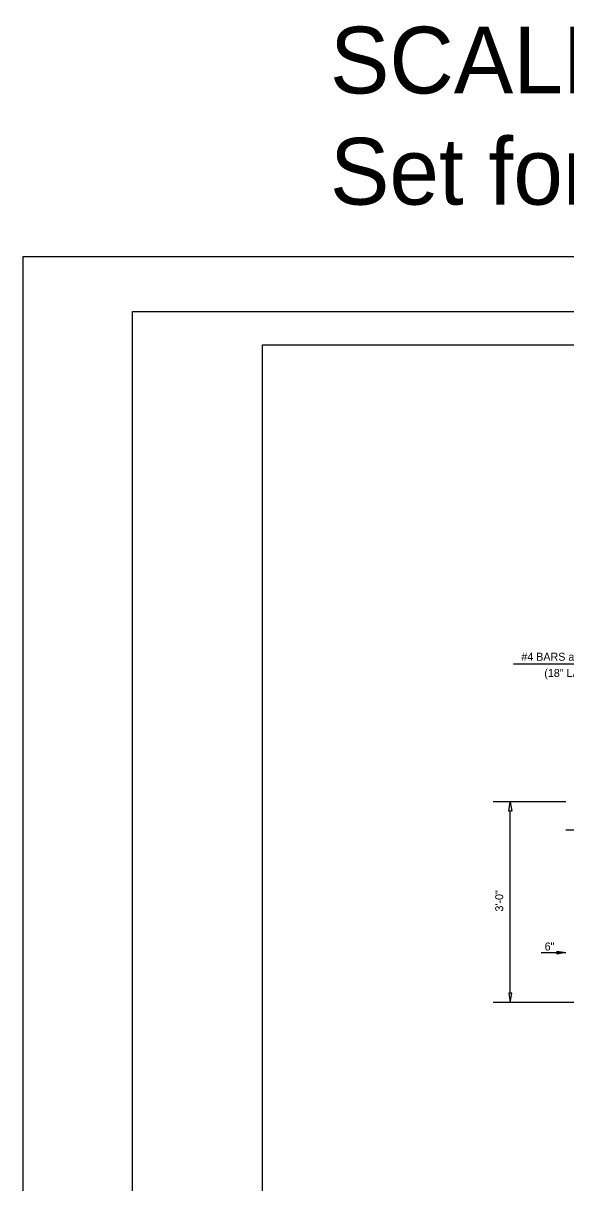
# Model space of a CAD drawing. Extents: x 570 to 2153298, y 726 to 139926.
# Drawn here: x 2153141.23 to 2153149.36, y 139607.73 to 139625.12 of the extents above; entities that cross this region are included whole.
import ezdxf

# ---------------------------------------------------------------- set-up
doc = ezdxf.new("R2010")
doc.units = 0
for name, color, linetype in [('4', 7, 'Continuous'), ('6', 7, 'Continuous'), ('Default', 7, 'Continuous'), ('PR_Dimensions', 7, 'Continuous'), ('PR_SlopeWall', 7, 'Continuous'), ('S', 7, 'Continuous'), ('SHT_Plot_Shape_Full', 7, 'Continuous'), ('SHT_Plot_Shape_Half', 7, 'Continuous'), ('SHT_Sheet_Border', 7, 'Continuous'), ('T', 7, 'Continuous')]:
    doc.layers.add(name, color=color, linetype=linetype)

# ---------------------------------------------------------------- blocks, each defined once
blk = doc.blocks.new('ARROWHD_15')
at = {"layer": 'Default'}
blk.add_lwpolyline([(0.0261, -0.0045), (0.0261, 0.0043), (-0.0004, -0.0001)], close=True, dxfattribs=at)

msp = doc.modelspace()

# ---------------------------------------------------------------- linework, layer by layer
at = {"layer": '4'}
msp.add_line((2153149.362, 139613.026), (2153149.862, 139613.026), dxfattribs=at)
at = {"layer": '6'}
for p, q in [((2153148.58, 139615.512), (2153151.721, 139615.512)), ((2153149.363, 139611.183), (2153148.994, 139611.183))]:
    msp.add_line(p, q, dxfattribs=at)
at = {"layer": 'Defpoints'}
for p, q in [((2153149.362, 139613.443), (2153148.275, 139613.443)), ((2153149.362, 139610.438), (2153148.275, 139610.438))]:
    msp.add_line(p, q, dxfattribs=at)
at = {"layer": 'PR_Dimensions'}
for p, q in [((2153149.323, 139613.443), (2153148.409, 139613.443)), ((2153148.529, 139610.578), (2153148.529, 139613.303)), ((2153149.242, 139610.438), (2153148.409, 139610.438))]:
    msp.add_line(p, q, dxfattribs=at)
for points in [[(2153148.552, 139613.303), (2153148.506, 139613.303), (2153148.529, 139613.443)], [(2153148.552, 139610.578), (2153148.506, 139610.578), (2153148.529, 139610.438)]]:
    msp.add_lwpolyline(points, close=True, dxfattribs=at)
at = {"layer": 'PR_SlopeWall'}
msp.add_line((2153150.362, 139610.438), (2153149.362, 139610.438), dxfattribs=at)
at = {"layer": 'SHT_Plot_Shape_Full'}
msp.add_lwpolyline([(2153141.225, 139621.622), (2153177.225, 139621.622), (2153177.225, 139597.622), (2153141.225, 139597.622)], close=True, dxfattribs=at)
at = {"layer": 'SHT_Plot_Shape_Half'}
msp.add_lwpolyline([(2153142.863, 139620.797), (2153176.863, 139620.797), (2153176.863, 139598.797), (2153142.863, 139598.797)], close=True, dxfattribs=at)
at = {"layer": 'SHT_Sheet_Border'}
msp.add_lwpolyline([(2153176.313, 139599.297), (2153144.813, 139599.297), (2153144.813, 139620.297), (2153176.313, 139620.297)], close=True, dxfattribs=at)

# ---------------------------------------------------------------- block references
at = {"layer": '6', "xscale": 4.7243995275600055, "yscale": -4.7243995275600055, "rotation": 180}
msp.add_blockref('ARROWHD_15', (2153149.358, 139611.184), dxfattribs=at)

# ---------------------------------------------------------------- texts
at = {"layer": 'S'}
for s, p in [('SCALE:  FULL 1" = 1\'-0" (SF=12) HALF 1/2 " = 1\'-0"', (2153145.825, 139624.065)), ('Set for Architectural Units', (2153145.825, 139622.398))]:
    msp.add_text(s, height=1.00003, dxfattribs=at).set_placement(p)
at = {"layer": 'T'}
for s, p in [('#4 BARS at 12" CTRS. CONTINUOUS', (2153148.696, 139615.56)), ('(18" LAP WHEN NECESSARY)', (2153149.04, 139615.316)), ('6"', (2153149.045, 139611.216))]:
    msp.add_text(s, height=0.12, dxfattribs=at).set_placement(p)
msp.add_text('3\'-0"', height=0.12, rotation=90, dxfattribs=at).set_placement((2153148.424, 139611.8))

doc.saveas('drawing.dxf')
